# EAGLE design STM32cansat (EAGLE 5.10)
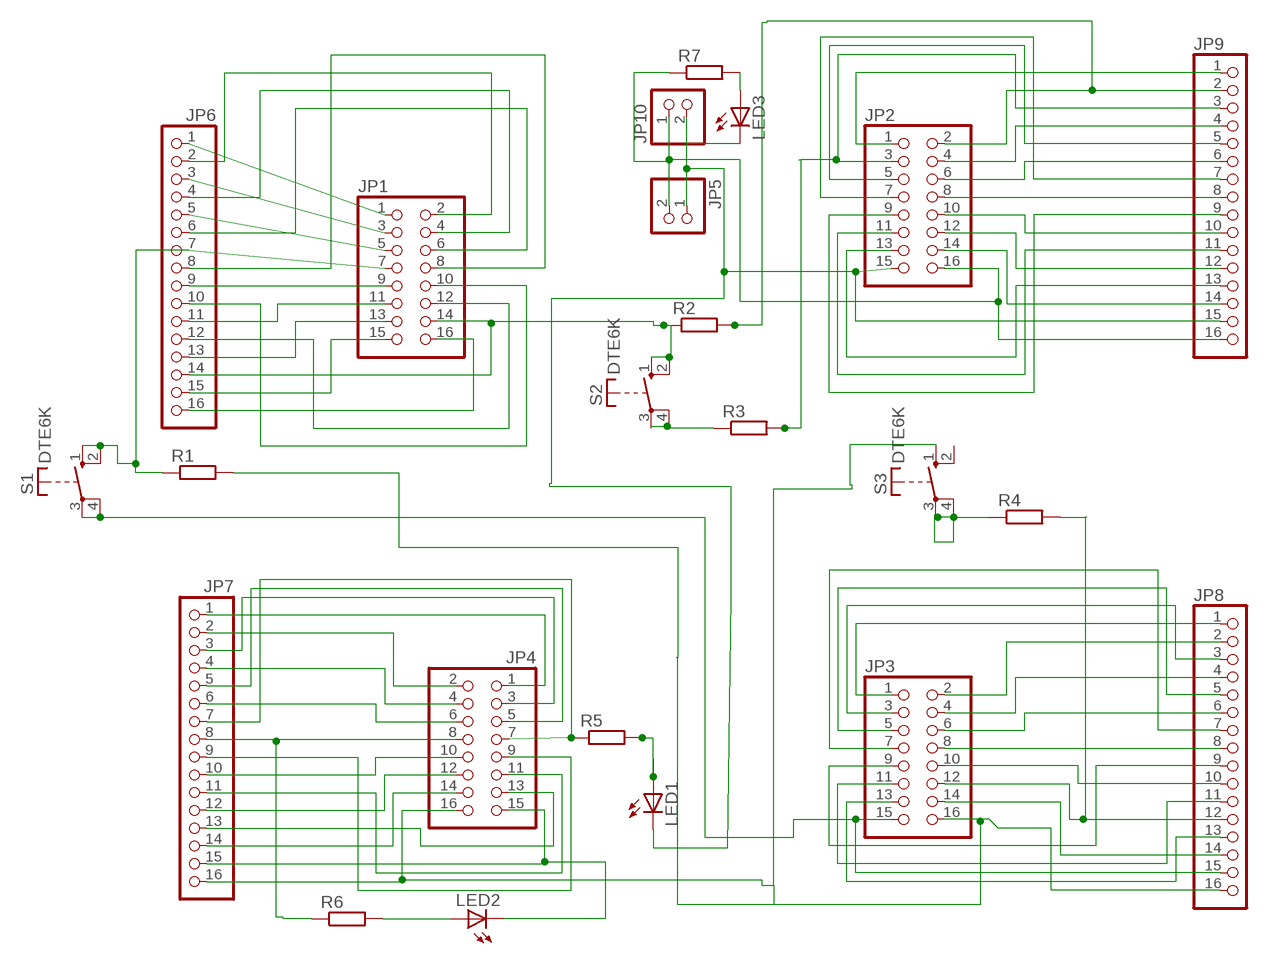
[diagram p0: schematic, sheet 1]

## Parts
JP1  PINHD-2X8  [2X08]
JP2  PINHD-2X8  [2X08]
JP3  PINHD-2X8  [2X08]
JP4  PINHD-2X8  [2X08]
JP5  PINHD-1X2  [1X02]
JP6  PINHD-1X16  [1X16]
JP7  PINHD-1X16  [1X16]
JP8  PINHD-1X16  [1X16]
JP9  PINHD-1X16  [1X16]
JP10  PINHD-1X2  [1X02]
LED1  LED3MM  [LED3MM]
LED2  LED3MM  [LED3MM]
LED3  LED3MM  [LED3MM]
R1  R-EU_0207/10  [0207/10]
R2  R-EU_0207/10  [0207/10]
R3  R-EU_0207/10  [0207/10]
R4  R-EU_0207/10  [0207/10]
R5  R-EU_0207/10  [0207/10]
R6  R-EU_0207/10  [0207/10]
R7  R-EU_0309/10  [0309/10]
S1  DTE6K  [DTE6K]
S2  DTE6K  [DTE6K]
S3  DTE6K  [DTE6K]

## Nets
N$1: JP1.1 JP6.1
N$3: JP1.2 JP6.2
N$4: JP1.3 JP6.3
N$6: JP1.4 JP6.4
N$7: JP1.5 JP6.5
N$8: JP1.6 JP6.6
N$9: JP1.7 JP6.7 R1.1 S1.1(S) S1.2(S)
N$10: JP1.8 JP6.8
N$11: JP1.9 JP6.9
N$12: JP1.11 JP6.11
N$13: JP1.13 JP6.13
N$14: JP1.15 JP6.15
N$15: JP1.16 JP6.16
N$16: JP1.14 JP6.14 R2.1 S2.1(S) S2.2(S)
N$17: JP1.12 JP6.12
N$18: JP1.10 JP6.10
N$19: JP2.8 JP9.8
N$20: JP2.6 JP9.6
N$21: JP2.4 JP9.4
N$22: R4.1 S3.4(P)
N$23: JP2.10 JP9.10
N$24: JP2.12 JP9.12
N$25: JP2.14 JP9.14
N$28: JP2.13 JP9.13
N$29: JP2.11 JP9.11
N$30: JP2.9 JP9.9
N$31: JP2.1 JP9.1
N$32: JP2.3 JP9.3 R3.2
N$33: JP2.5 JP9.5
N$34: JP2.7 JP9.7
N$35: JP4.8 JP7.8 R6.1
N$36: JP4.6 JP7.6
N$37: JP4.4 JP7.4
N$38: JP4.2 JP7.2
N$39: JP4.10 JP7.10
N$40: JP4.12 JP7.12
N$41: JP4.14 JP7.14
N$44: JP4.13 JP7.13
N$45: JP4.11 JP7.11
N$46: JP4.9 JP7.9
N$47: JP4.1 JP7.1
N$49: JP4.3 JP7.3
N$50: JP4.5 JP7.5
N$51: JP4.7 JP7.7 R5.1
N$54: JP3.8 JP8.8
N$55: JP3.6 JP8.6
N$56: JP3.4 JP8.4
N$57: JP3.2 JP8.2
N$58: JP3.1 JP8.1
N$59: JP3.3 JP8.3
N$60: JP3.5 JP8.5
N$61: JP3.7 JP8.7
N$62: JP3.10 JP8.10
N$63: JP3.12 JP8.12 R4.2
N$64: JP3.14 JP8.14
N$68: JP3.16 JP4.16 JP7.16 JP8.16 R1.2 S3.1(S)
N$126: S3.3(P)
N$129: JP3.13 JP8.13
N$130: JP3.11 JP8.11
N$131: JP3.9 JP8.9
N$137: JP3.15 JP8.15 S1.3(P) S1.4(P)
N$144: JP2.2 JP9.2 R2.2
N$151: R3.1 S2.4(P)
N$157: LED2.A R6.2
N$159: LED1.A R5.2
N$203: LED3.A R7.2
N$210: JP2.15 JP5.1 JP9.15 JP10.2 LED1.K(C) LED3.K(C)
N$212: JP2.16 JP5.2 JP9.16 JP10.1 R7.1
N$221: JP4.15 JP7.15 LED2.K(C)
Unconnected: S2.3(P) S3.2(S)

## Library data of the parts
JP1-JP4 = pinhead:PINHD-2X8: PIN HEADER
JP5 JP10 = pinhead:PINHD-1X2: PIN HEADER
JP6-JP9 = pinhead:PINHD-1X16: PIN HEADER
LED1-LED3 = led:LED: LED
R1-R7 = rcl:R-EU_: RESISTOR, European symbol
S1-S3 = switch-misc:DT: ITT SWITCH

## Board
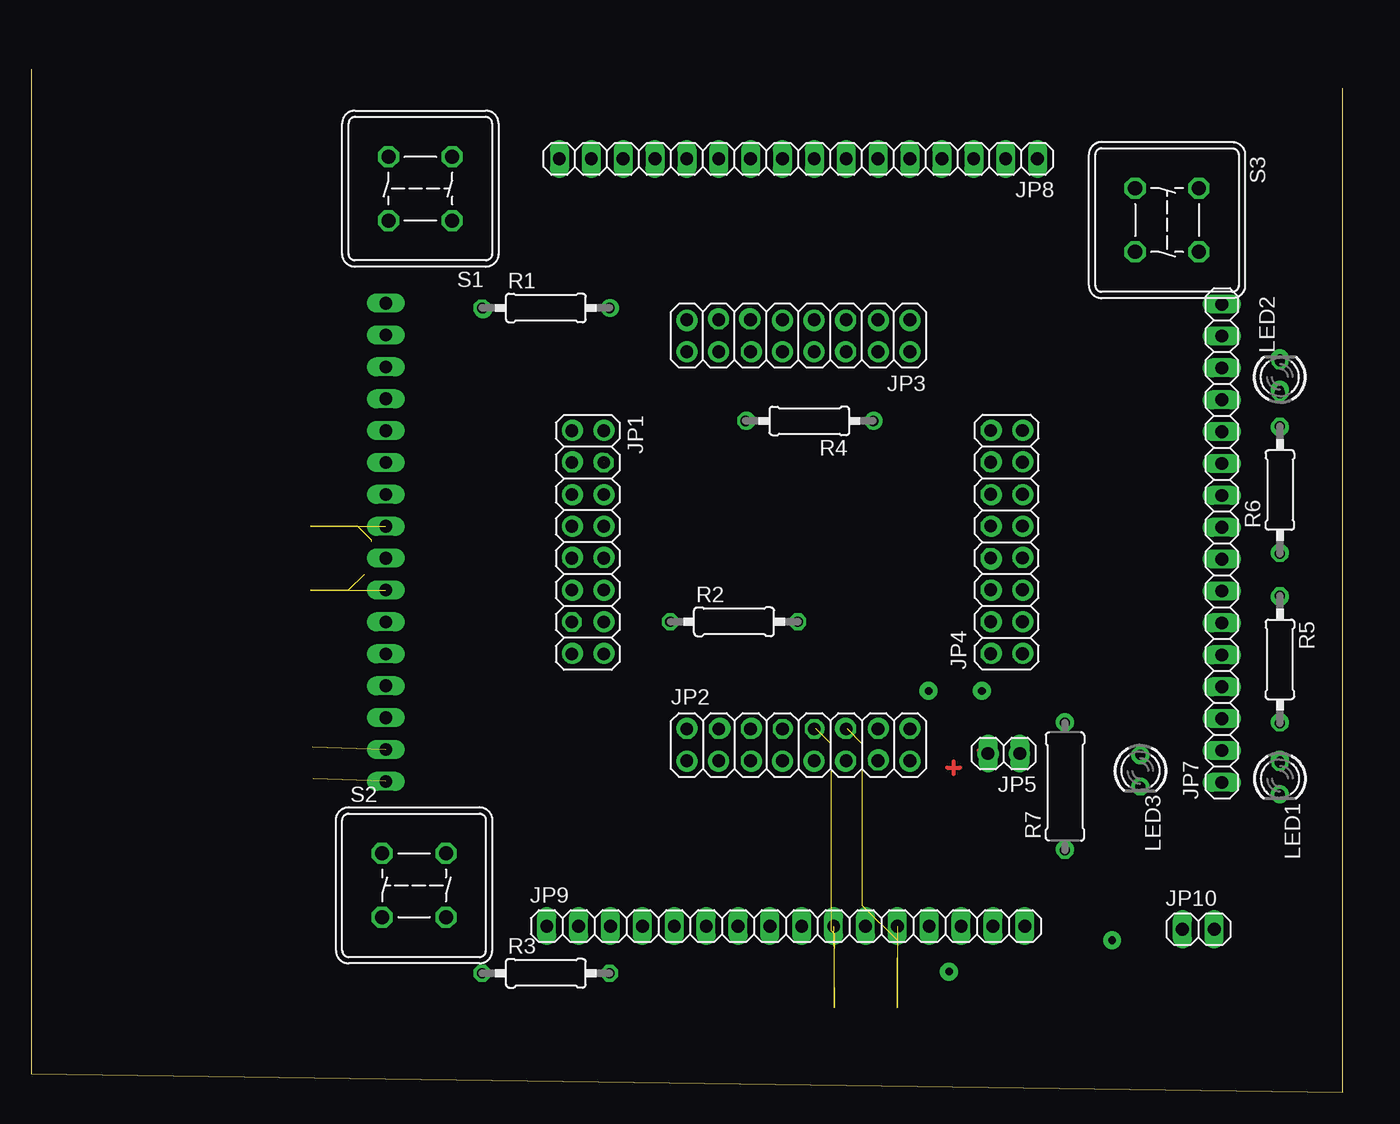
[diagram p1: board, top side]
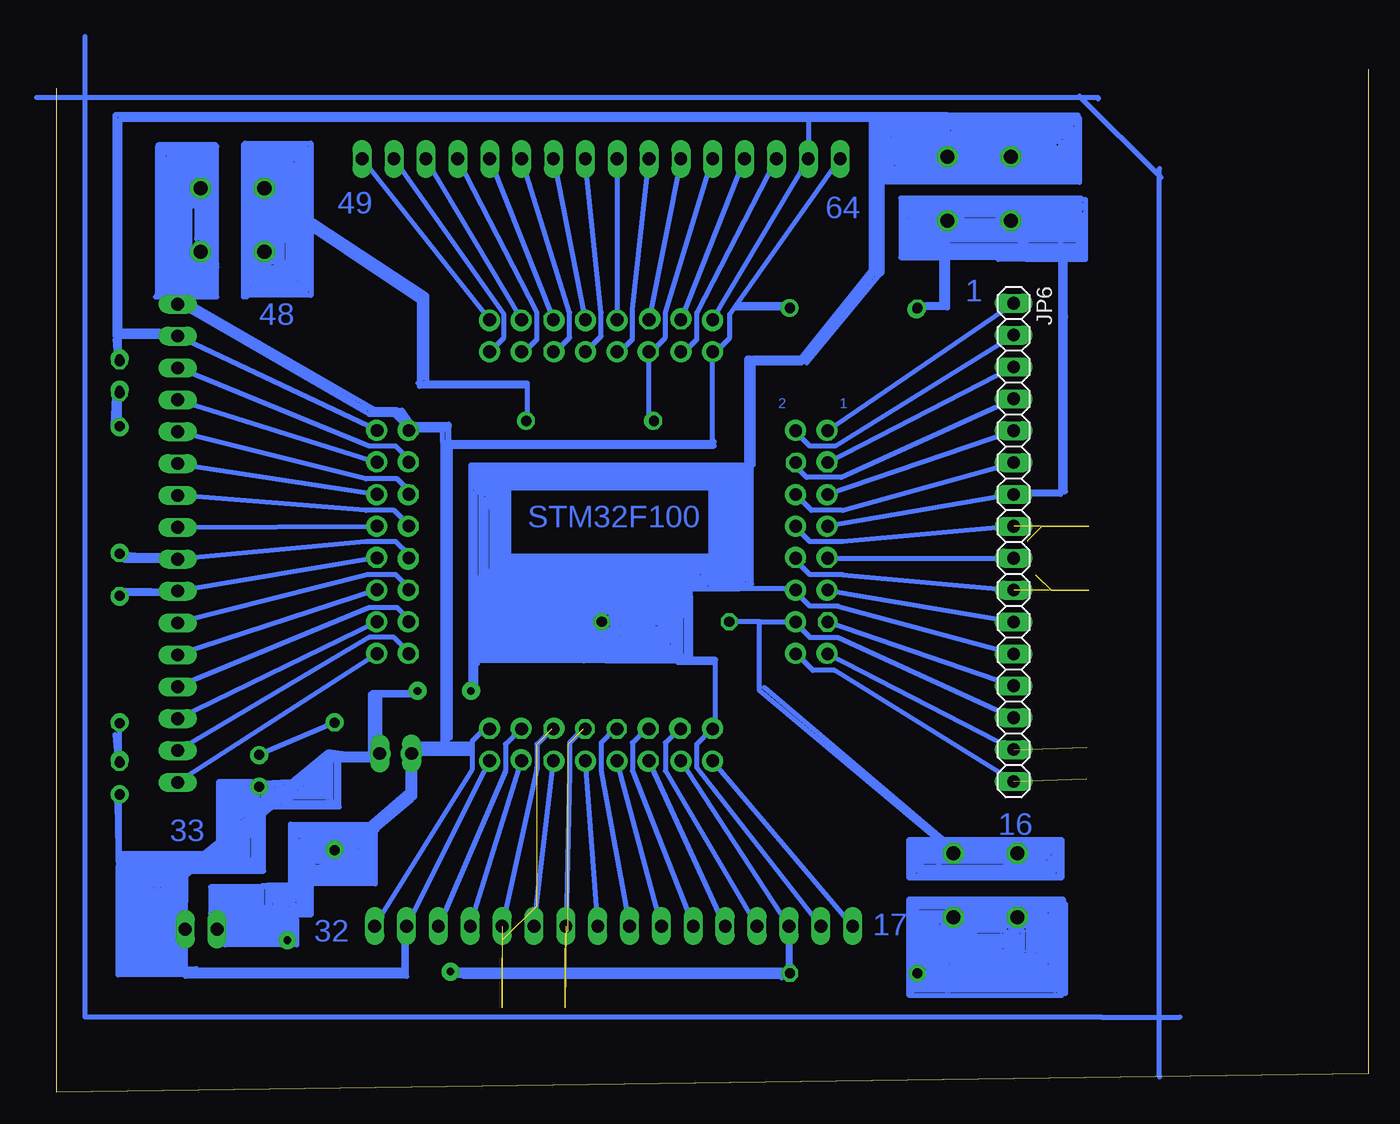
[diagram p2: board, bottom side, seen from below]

Size 104.5 x 81.5 mm. Coordinates in mm from the lower left corner, seen from the top.
Outline: 104.5,80 104.5,0 0,1.5 0,81.5
Copper layers (1*16): Top 0.035mm / dielectric 1.5mm / Bottom 0.035mm
Design rules "default": minimum track width 10mil, minimum drill 24mil, track to track 8mil, track to pad 8mil, pad to pad 8mil, via to via 8mil, smd to smd 8mil, copper to edge 40mil, drill to drill 8mil, minimum pad ring 10mil, minimum via ring 8mil, stop-mask expansion 4mil, vias tented up to drill 0mil, thermal gap 10mil

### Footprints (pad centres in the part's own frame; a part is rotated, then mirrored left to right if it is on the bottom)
2X08 = drill 1.016 octagon: 1 -8.89,-1.27; 2 -8.89,1.27; 3 -6.35,-1.27; 4 -6.35,1.27; 5 -3.81,-1.27; 6 -3.81,1.27; 7 -1.27,-1.27; 8 -1.27,1.27; 9 1.27,-1.27; 10 1.27,1.27; 11 3.81,-1.27; 12 3.81,1.27; 13 6.35,-1.27; 14 6.35,1.27; 15 8.89,-1.27; 16 8.89,1.27
1X02 = drill 1.016 long: 1 -1.27,0; 2 1.27,0
1X16 = drill 1.016 long: 1 -19.05,0; 2 -16.51,0; 3 -13.97,0; 4 -11.43,0; 5 -8.89,0; 6 -6.35,0; 7 -3.81,0; 8 -1.27,0; 9 1.27,0; 10 3.81,0; 11 6.35,0; 12 8.89,0; 13 11.43,0; 14 13.97,0; 15 16.51,0; 16 19.05,0
LED3MM = drill 0.813 octagon: A -1.27,0; K 1.27,0
0207/10 = drill 0.813 octagon: 1 -5.08,0; 2 5.08,0
0309/10 = drill 0.813 octagon: 1 -5.08,0; 2 5.08,0
DTE6K = drill 1.118 octagon: 1 -2.54,2.54; 2 2.54,2.54; 3 2.54,-2.54; 4 -2.54,-2.54

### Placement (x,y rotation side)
JP1  44.34,43.83 270 top
JP2  61.12,27.69 0 top
JP3  61.12,60.28 180 top
JP4  77.72,43.85 90 top
JP5  77.5,27 180 top
JP6  28.25,43.83 270 bottom
JP7  94.88,43.75 90 top
JP8  61.12,74.38 180 top
JP9  60.12,13.25 0 top
JP10  93,13 0 top
LED1  99.5,25 270 top
LED2  99.5,57 90 top
LED3  88.38,25.62 270 top
R1  41,62.5 0 top
R2  56,37.5 0 top
R3  41,9.5 0 top
R4  62,53.5 180 top
R5  99.5,34.5 270 top
R6  99.5,48 90 top
R7  82.38,24.38 90 top
S1  31,72 180 top
S2  30.5,16.5 0 top
S3  90.5,69.5 270 top

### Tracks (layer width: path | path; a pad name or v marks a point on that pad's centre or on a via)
N$1
  Bottom 0.406: JP1.1 JP6.1
N$2
  Top 0.305: 75.62,27.12 75.5,27.25
N$3
  Bottom 0.406: JP1.2 45.62,52.62 44.5,51.5 42.5,51.5 JP6.2
N$4
  Bottom 0.406: JP1.3 JP6.3
N$5  (via drill 0.6 pad 1.68)
  other vias: 76.25,27
N$6
  Bottom 0.406: JP1.4 45.62,49.87 44.75,49 42,49 JP6.4
N$7
  Bottom 0.406: JP1.5 JP6.5
N$8
  Bottom 0.406: JP1.6 45.62,47.62 44.38,46.38 41.88,46.38 JP6.6
N$9
  Bottom 0.406: JP1.7 JP6.7 24.5,47.64 24.5,69.5 28.46,69.5 S1.2 S1.1 33.54,62.5 | 33.54,62.5 R1.1 | 33.54,62.5 33.5,62.5
N$10  (4 unrouted)
  Bottom 0.406: JP1.8 45.62,44.99 44.5,43.88 41.88,43.88 JP6.8
N$11
  Bottom 0.406: JP1.9 JP6.9
N$12
  Bottom 0.406: JP1.11 JP6.11
N$13
  Bottom 0.406: JP1.13 JP6.13
N$14  (1 unrouted)
  Bottom 0.406: JP6.15 JP1.15
N$15  (1 unrouted)
  Bottom 0.406: JP1.16 45.56,34.94 44.25,33.62 42.5,33.62 JP6.16
N$16
  Bottom 0.406: JP6.14 42.25,36.25 44.5,36.25 45.62,37.37 JP1.14 48.5,37.48 | 48.5,37.48 48.5,37.5 | 48.5,37.48 48.5,32 S2.2 S2.1 | 48.5,37.48 R2.1
N$17
  Bottom 0.406: JP1.12 45.62,39.87 44.5,38.75 42.25,38.75 JP6.12
N$18  (3 unrouted)
  Bottom 0.406: JP1.10 45.62,42.37 44.5,41.25 41.88,41.25 JP6.10
N$19
  Bottom 0.406: JP2.8 60.04,28.96 61.12,27.88 61.12,25.62 JP9.8
N$20
  Bottom 0.406: JP2.6 57.54,28.96 58.62,27.88 58.62,25.62 JP9.6
N$21
  Bottom 0.406: JP2.4 54.91,28.96 56,27.88 56,25.62 JP9.4
N$22
  Bottom 0.406: R4.1 67,53.5 67,56.5 | 67,56.5 75,56.5 | 75,56.5 75,63.5 S3.4 | 75.75,56.5 75,56.5 | 67,56.5 67.12,56.25 75.62,56.25 75.62,58 | 75.62,63.38 75.62,58 | 75.62,58 75.5,57.5
N$23  (6 unrouted)
  Bottom 0.406: JP2.10 62.54,28.96 63.62,27.88 63.62,25.5 JP9.10
N$24  (6 unrouted)
  Bottom 0.406: JP2.12 65.04,28.96 66.25,27.75 66.25,25.88 JP9.12
N$25
  Bottom 0.406: JP2.14 67.54,28.96 68.75,27.75 68.75,25.62 JP9.14
N$27
  Bottom 0.406: 87.25,73.12 88.75,73.12 88.75,72.88 | 87.38,67.62 87.38,70.88 87.62,70.88 | 89.62,63.38 89.62,75.5 89.5,75.62 84.25,75.62 84.25,63.5 89.25,63.5 89.38,63.38 89.38,75.38 84.75,75.38 84.62,75.25 84.62,63.88 89.25,63.88 89.25,75 85,75 84.88,75.12 84.88,64.38 85.12,64.12 88.75,64.12 89,64.38 89,72.38 89,72.88 | 89,72.88 89,74.75 85.25,74.75 85.12,74.62 85.12,64.38 88.62,64.38 88.62,72.62 | 88.62,72.88 88.62,74.25 88.75,74.38 85.38,74.38 85.38,64.88 85.62,64.62 88.38,64.62 88.5,64.75 88.5,67.38 89.12,68 88.5,68 88.25,67.75 88.25,71 88.38,71.12 85.62,71.12 85.62,65.12 85.88,64.88 88.12,64.88 88.12,65.62 | 88.12,65.62 88.12,66.12 87.5,66.12 | 87.12,66.12 85.75,66.12 85.75,65.5 86,65.25 88,65.25 88,65.62 87.88,65.75 86.38,65.75 | 86.12,65.75 86,65.88 86,65.62 86.75,65.62 | 88.12,65.62 86.75,65.62 | 86.75,65.62 86.38,66 | 86.38,66 85.88,66.5 85.88,67.88 | 85.88,67.88 85.88,73.88 86,74 85.75,74 85.75,71.88 85.62,71.75 87,71.75 87.12,71.62 86,71.62 85.75,71.38 85.75,71.5 86.75,71.5 87,71.25 87.38,71.25 87.75,70.88 | 87.75,70.88 87.88,70.75 87.88,68 87.75,67.88 86.12,67.88 | 85.88,67.88 86.12,67.88 | 86.12,67.88 86.12,74 88.5,74 88.5,73.62 86.12,73.62 86.12,65.75 | 86.12,65.75 86.38,65.75 | 86.38,65.75 86.38,66 | 86.38,66 86.5,66 86.5,73.88 86.62,73.88 | 86.88,73.88 86.62,73.88 | 86.62,73.88 86.62,66 87,66 87,72.62 | 87,72.62 87,72.88 | 87,72.88 87,73.75 87.38,73.75 87.38,73.25 87.12,73.25 87.12,66.12 | 87.12,66.12 87.5,66.12 | 87.5,66.12 87.5,66.25 | 87.75,70.88 87.62,70.88 | 87.62,70.88 87.62,68.12 | 87,72.62 88.62,72.62 | 88.62,72.62 88.62,72.88 | 88.62,72.88 88.5,72.88 88.5,73.38 87.5,73.38
  Bottom 0.406: 88.75,72.88 87,72.88 | 88.75,72.88 89,72.88
N$28
  Bottom 0.406: JP9.13 JP2.13
N$29
  Bottom 0.406: JP9.11 JP2.11
N$30
  Bottom 0.406: JP2.9 JP9.9
N$31
  Bottom 0.406: JP9.1 JP2.1
N$32
  Bottom 0.406: JP2.3 JP9.3 46.08,13.25 R3.2
N$33
  Bottom 0.406: JP9.5 JP2.5
N$34
  Bottom 0.406: JP9.7 JP2.7
N$35
  Bottom 0.406: JP4.8 76.44,42.82 77.5,43.88 79.88,43.88 JP7.8 R6.1
N$36
  Bottom 0.406: JP4.6 76.44,40.2 77.5,41.25 79.75,41.25 JP7.6
N$37
  Bottom 0.406: JP4.4 76.44,37.7 77.38,38.62 79.62,38.62 JP7.4
N$38
  Bottom 0.406: JP4.2 76.42,34.96 76.38,35 77.62,36.25 79.62,36.25 JP7.2
N$39
  Bottom 0.406: JP4.10 76.44,45.2 77.62,46.38 79.88,46.38 JP7.10
N$40
  Bottom 0.406: JP4.12 76.44,47.95 77.38,48.88 79.88,48.88 JP7.12
N$41
  Bottom 0.406: JP4.14 76.44,50.45 77.5,51.5 79.62,51.5 JP7.14
N$42
  Bottom 0.406: 92.62,73.25 95.25,73.25 | 95.25,73.25 95.38,73.25 95.38,73.38 95.25,73.38 95.25,73.25 | 95.25,73.25 95.25,72.12 95,72.12 95,73 92.75,73
N$43  (via drill 0.6 pad 1.42)
  Bottom 0.406: 61.12,37.62 61.25,37.62 61.25,37.88 | 61.25,37.88 61.25,40.12 | 45.75,40.12 50.12,40.12 | v71.5,32 71.5,36.12 | 71.5,36.62 71.5,50 50.12,50 | 50,50 49,50 49,58.5 45.25,58.5 39.62,65.5 39.62,77.38 39.38,77.38 | 50.12,40.25 50.12,50 | 50.12,50 50,50 | 50,50 50,49.75 | 61.25,40.12 50.12,40.12 | 50.12,40.12 50.12,40.25 | 50.12,40.25 52.38,40.25 52.38,42.62 | 52.38,42.75 52.38,48.75 | 52.38,48.75 52.38,48.88 | 52.38,49.12 52.38,49.62 50.38,49.62 50.38,40.62 51.88,40.62 51.88,40.5 52.12,40.5 52.12,49.5 51.75,49.5 | 51.62,49.5 50.75,49.5 50.75,41.12 50.5,41.12 50.5,41 51.75,41 51.75,40.88 51.62,40.88 51.62,41.5 | 51.62,48.12 51.62,49.5 | 51.62,49.5 51.75,49.5 | 51.75,49.5 51.75,49.25 50.88,49.25 50.88,41.25 51.12,41.25 | 51.38,41.25 51.12,41.25 | 51.12,41.25 51.12,48.88 51.5,48.88 51.5,41.5 51.62,41.5 | 51.62,41.5 51.62,48.12 | 51.62,48.12 68.5,48.12 | 68.62,48.12 71.12,48.12 71.12,49.75 52.5,49.75 52.5,49.38 71,49.38 71,49 52.38,49 | 52.38,49 52.38,48.88 | 52.38,48.88 52.62,48.88 52.62,48.5 68.62,48.5 | 70.88,48.5 68.62,48.5 | 68.62,48.5 68.62,48.12 | 68.62,48.12 68.5,48.12 | 68.5,48.12 68.5,42.75 52.38,42.75 | 52.38,42.75 52.38,42.62 | 52.38,42.62 52.75,42.62 52.75,42.5 | 52.75,42.5 52.75,40.5 71.12,40.5 | 71.12,40.5 71.12,40.38 | 71.12,40.5 71.12,41 | 71.12,41 71.12,47.88 68.88,47.88 68.88,42.25 53,42.25 53,41 58.88,41 | 58.88,41 70.62,41 | 71.12,41 70.62,41 | 70.62,41 70.62,47.75 69.25,47.75 69.25,42 53.25,42 53.25,41.88 53.38,41.88 53.38,41.38 70.25,41.38 | 70.25,41.38 70.25,41.25 | 70.25,41.38 70.25,47.38 69.62,47.38 | 69.62,47.38 69.62,47.5 | 69.62,47.38 69.62,41.75 52.62,41.75 52.62,41.5 49.88,41.5 | 49.88,40.88 49.88,40.5 49.12,40.5 49.12,49.88 49.5,49.88
  Bottom 0.406: 49.5,49.88 49.5,40.88 49.88,40.88 | 49.88,41.5 49.88,40.88 | 49.88,41.5 49.88,49.38 49.62,49.38 49.62,49.88 49.5,49.88 | 49.5,49.88 49.5,58.5 49.38,58.5 | 49.25,58.5 49.38,58.5 | 49.38,58.5 49.38,49.62 70,49.62 70,46.62 69.88,46.62 69.88,41.62 61.38,41.62 61.38,40.38 61.25,40.38 61.25,40.12 | 61.25,37.88 71.25,37.88 71.25,38 71.12,38 71.12,40.25 71,40.25 | 70.75,40.25 61.38,40.25 61.38,40 61.5,40 61.5,38 61.88,38 | 70.25,38 70.62,38 70.62,38.62 | 70.62,38.62 70.62,39.62 | 70.62,39.62 70.62,39.88 | 70.62,39.88 70.38,39.88 | 70.38,39.88 61.88,39.88 | 61.88,39.88 61.88,38 | 61.88,38 70.25,38 | 70.25,38 70.25,38.62 70.38,38.62 70.38,39.38 62,39.38 | 62,39.38 62,39.5 | 62,39.38 62,38.25 70,38.25 70,38.38 70.38,38.38 70.38,39.88 | 61.88,39.88 54.38,39.88 | 54.38,39.88 54.38,40 | 54.38,39.88 54.38,34.75 71.38,34.75 71.38,34.5 71.25,34.5 | 71.25,34.5 71.25,38.12 70.12,38.12 70.12,38.88 | 70.12,38.88 70.12,39.12 54.25,39.12 | 54,39.12 54.25,39.12 | 54.25,39.12 54.25,39.5 | 54.25,39.5 61.12,39.5 | 54.25,39.5 54,39.5 | 54,39.5 54,40.38 | 54,39.5 54,34.75 60.75,34.75 60.75,34.38 | 60.75,34.38 62.5,34.38 | 62.5,34.38 71.25,34.38 71.25,34.5 | 71.25,34.5 62.5,34.5 62.5,34.38 | 60.75,34.38 52.12,34.38 52.12,34.25 55,34.25 55,34.62 54.75,34.62 54.75,38.38 | 54.75,38.5 54.75,38.88 69.88,38.88 | 70.12,38.88 69.88,38.88 | 69.88,38.88 69.88,38.38 54.75,38.38 | 54.62,38 54.62,38.38 54.75,38.38 | 54.75,38.38 54.75,38.5 | 54.75,38.5 54.62,38.5 54.62,38.62 70.62,38.62 | 70.62,38.62 71,38.62 71,36.62 | 71,35.88 71,35.12 55,35.12 55,38.25 70.75,38.25 70.75,35.5 61.25,35.5 | 60.75,35.5 55.38,35.5 | 55.38,35.5 55.38,35.38 | 55.38,35.5 55.38,38 60.38,38 60.38,37.38 60.25,37.38 60.25,35.62 60.5,35.62 60.5,36.88 60.75,36.88
  Bottom 0.406: 60.88,36.88 60.75,36.88 | 60.75,36.88 60.75,35.88 | 60.75,35.88 55.75,35.88 55.75,37.88 60.12,37.88 60.12,36 56,36 56,37.62 59.88,37.62 59.88,36.12 56.62,36.12 56.62,36.25 56.38,36.25 56.38,37.38 60,37.38 60,37 | 60,37 59.5,37 | 59.5,37 59.5,36.5 | 59.5,36.5 59.25,36.5 | 59.25,36.5 56.88,36.5 | 56.88,36.5 56.88,37 | 56.88,37 56.5,37 | 56.88,37 59.5,37 | 60,37 60,36.12 71.5,36.12 | 71.5,36.12 71.5,36.62 | 71.5,36.62 71,36.62 | 71,36.62 71,35.88 | 71,35.88 60.75,35.88 | 60.75,35.88 60.75,35.5 | 60.75,35.5 61.25,35.5 | 61.25,35.5 61.25,36.88 70.62,36.88 | 70.62,36.88 70.62,37 | 70.62,36.88 70.62,36.62 61.75,36.62 | 61.38,36.62 61.75,36.62 | 61.75,36.62 61.75,37.62 70.38,37.62 70.38,37.25 61.62,37.25 61.62,37.38 | 56.12,36.88 59.25,36.88 59.25,36.5 | 56.88,36.5 56.5,36.5 | 59.5,36.5 70.62,36.5 70.62,36.25 71,36.25 71,40 70.62,40 70.62,39.88 | 70.62,39.62 59,39.62 59,40.75 51.88,40.75 51.88,41.62 52,41.62 52,49.12 52.38,49.12 | 52.38,49.12 52.38,49 | 52.38,48.75 71,48.75 71,48.62 70.75,48.62 70.75,40.25 | 70.75,40.25 71,40.25 | 71,40.25 71,40.75 58.88,40.75 58.88,41 | 52.75,42.5 69.38,42.5
N$44
  Bottom 0.406: JP7.13 JP4.13
N$45
  Bottom 0.406: JP7.11 JP4.11
N$46
  Bottom 0.406: JP7.9 JP4.9
N$47
  Bottom 0.406: JP4.1 JP7.1
N$48  (via drill 0.6 pad 1.68)
  other vias: 78.75,27
N$49
  Bottom 0.406: JP4.3 JP7.3
N$50
  Bottom 0.406: JP4.5 JP7.5
N$51
  Bottom 0.406: JP4.7 JP7.7 99,40 R5.1
N$52
  Bottom 0.406: 102.25,84.12 102.25,6 21.5,6 21.25,6 15,6
N$53
  Bottom 0.406: 106.12,79.25 21.5,79.25 21.5,79.12
N$54
  Bottom 0.406: JP3.8 62.37,59.01 61.12,60.25 61.12,62.12 JP8.8
N$55
  Bottom 0.406: JP3.6 64.74,59.01 63.62,60.12 63.62,62.12 JP8.6
N$56
  Bottom 0.406: JP3.4 67.24,59.01 66.25,60 66.25,62.12 JP8.4
N$57
  Bottom 0.406: JP3.2 69.99,59.01 68.88,60.12 68.88,62 JP8.2
N$58
  Bottom 0.406: JP8.1 JP3.1
N$59
  Bottom 0.406: JP8.3 JP3.3
N$60
  Bottom 0.406: JP8.5 JP3.5
N$61
  Bottom 0.406: JP8.7 JP3.7
N$62
  Bottom 0.406: JP3.10 59.62,59.01 58.62,60 58.62,62.38 JP8.10
N$63  (via drill 0.6 pad 1.42)
  Bottom 0.406: JP8.12 56,62.12 56,60.12 57.12,59.01 JP3.12 57.31,53.5 v57,53.5 R4.2
N$64
  Bottom 0.406: JP3.14 54.49,59.01 53.5,60 53.5,62.12 JP8.14
N$65  (via drill 0.7 pad 1.68)
  other vias: 43.12,52.75
N$66  (via drill 0.7 pad 1.68)
  other vias: 45.62,52.75
N$67  (1 unrouted)
N$68  (via drill 0.6 pad 1.42)
  Bottom 0.406: 73.38,28.25 73.12,28.25 73.12,51.88 73.25,51.88 | 73.25,51.88 73.38,51.88 | S3.1 95,72 95,63.5 JP7.16 79.62,54 77.62,54 76.44,52.82 JP4.16 73.75,52.75 73.75,51.75 | 50.34,62.74 50.88,62 50.88,60.12 51.99,59.01 JP3.16 52.25,51.75 73.75,51.75 | 50.34,62.74 JP8.16 | R1.2 v46.12,62.5 50.34,62.5 50.34,62.74 | 75.5,27.25 71.75,27.25 | 71.75,27.75 71.5,27.75 71.5,27.25 71.75,27.25 | 72,27.75 75.75,27.75 75.75,27.5 | 71.75,27.25 71.75,27.75 | 71.75,27.75 72,27.75 | 72,27.75 72,27.5 73.38,27.5 | 73.38,27.5 73.75,27.5 | 73.75,27.5 75.75,27.5 | 75.75,27.5 76,27.5 76,23.5 76.5,23.5 | 76.5,23.5 76.5,23.25 | 76.5,23.5 76.5,24 | 76.5,24 76.5,26.25 | 73.75,51.75 73.75,27.5 | 73.38,51.88 73.38,51.5 | 73.38,27.5 73.38,51.5 | 73.38,51.5 52.12,51.5 52.12,51.88 | 73.25,51.88 73.25,52.88 73.5,52.88 73.5,53 76.12,53 76.12,53.25 73.25,53.25 73.25,53 73.38,53 73.38,51.88 | 88.88,13.38 76.5,24 | 76.5,24 89.12,13.12
N$69  (via drill 0.7 pad 1.68)
  other vias: 45.62,47.62
N$70  (via drill 0.7 pad 1.68)
  other vias: 45.62,45.12
N$71  (via drill 0.7 pad 1.68)
  other vias: 45.62,42.62
N$72  (via drill 0.7 pad 1.68)
  other vias: 43.12,42.62
N$73  (via drill 0.7 pad 1.68)
  other vias: 43.12,45.12
N$74  (via drill 0.7 pad 1.68)
  other vias: 43.12,47.62
N$75  (via drill 0.7 pad 1.68)
  other vias: 45.62,40
N$76  (via drill 0.7 pad 1.68)
  other vias: 45.62,37.5
N$77  (via drill 0.7 pad 1.68)
  other vias: 45.62,35
N$78  (via drill 0.7 pad 1.68)
  other vias: 43.12,35
N$79  (via drill 0.7 pad 1.68)
  other vias: 43.12,40
N$80  (via drill 0.7 pad 1.68)
  other vias: 52.25,29
N$81  (via drill 0.7 pad 1.68)
  other vias: 54.88,29
N$82  (via drill 0.7 pad 1.68)
  other vias: 57.38,29
N$83  (via drill 0.7 pad 1.68)
  other vias: 62.38,26.38
N$84  (via drill 0.7 pad 1.68)
  other vias: 59.88,26.38
N$85  (via drill 0.7 pad 1.68)
  other vias: 57.38,26.38
N$86  (via drill 0.7 pad 1.68)
  other vias: 54.75,26.38
N$87  (via drill 0.7 pad 1.68)
  other vias: 52.25,26.38
N$88  (via drill 0.7 pad 1.68)
  other vias: 64.88,29
N$89  (via drill 0.7 pad 1.68)
  other vias: 67.5,29
N$90  (via drill 0.7 pad 1.68)
  other vias: 70,29
N$91  (via drill 0.7 pad 1.68)
  other vias: 70,26.38
N$92  (via drill 0.7 pad 1.68)
  other vias: 67.5,26.5
N$93  (via drill 0.7 pad 1.68)
  other vias: 64.88,26.38
N$94  (via drill 0.7 pad 1.68)
  other vias: 76.5,35
N$95  (via drill 0.7 pad 1.68)
  other vias: 79,35
N$96  (via drill 0.7 pad 1.68)
  other vias: 79,37.5
N$97  (via drill 0.7 pad 1.68)
  other vias: 79,40
N$98  (via drill 0.7 pad 1.68)
  other vias: 79,42.62
N$99  (via drill 0.7 pad 1.68)
  other vias: 79,45.12
N$100  (via drill 0.7 pad 1.68)
  other vias: 76.5,37.5
N$101  (via drill 0.7 pad 1.68)
  other vias: 76.5,40
N$102  (via drill 0.7 pad 1.68)
  other vias: 76.5,42.5
N$103  (via drill 0.7 pad 1.68)
  other vias: 76.5,45.12
N$104  (via drill 0.7 pad 1.68)
  other vias: 79,47.62
N$105  (via drill 0.7 pad 1.68)
  other vias: 76.5,47.62
N$106  (via drill 0.7 pad 1.68)
  other vias: 76.5,50.25
N$107  (via drill 0.7 pad 1.68)
  other vias: 79,50.25
N$108  (via drill 0.7 pad 1.68)
  other vias: 79,52.75
N$109  (via drill 0.7 pad 1.68)
  other vias: 76.5,52.75
N$110  (via drill 0.7 pad 1.68)
  other vias: 70,59
N$111  (via drill 0.7 pad 1.68)
  other vias: 70,61.5
N$112  (via drill 0.7 pad 1.68)
  other vias: 67.5,59
N$113  (via drill 0.7 pad 1.68)
  other vias: 67.5,61.5
N$114  (via drill 0.7 pad 1.68)
  other vias: 64.88,59
N$115  (via drill 0.7 pad 1.68)
  other vias: 64.88,61.5
N$116  (via drill 0.7 pad 1.68)
  other vias: 62.38,61.5
N$117  (via drill 0.7 pad 1.68)
  other vias: 62.38,59
N$118  (via drill 0.7 pad 1.68)
  other vias: 59.88,59
N$119  (via drill 0.7 pad 1.68)
  other vias: 59.88,61.5
N$120  (via drill 0.7 pad 1.68)
  other vias: 57.25,61.62
N$121  (via drill 0.7 pad 1.68)
  other vias: 57.38,59
N$122  (via drill 0.7 pad 1.68)
  other vias: 54.75,59
N$123  (via drill 0.7 pad 1.68)
  other vias: 54.75,61.62
N$124  (via drill 0.7 pad 1.68)
  other vias: 52.25,59
N$125  (via drill 0.7 pad 1.68)
  other vias: 52.25,61.5
N$127
  Top 0.305: 73,25.88 74,25.88
N$128
  Top 0.305: 73.5,26.38 73.5,25.38
N$129
  Bottom 0.406: JP8.13 JP3.13
N$130
  Bottom 0.406: JP8.11 JP3.11
N$131
  Bottom 0.406: JP8.9 JP3.9
N$132
  Bottom 0.406: 16.62,1.25 16.62,73.62
N$133  (via drill 0.6 pad 1.42)
  other vias: 43,37.5
N$134  (via drill 0.6 pad 1.42)
  other vias: 60,29
N$135  (via drill 0.6 pad 1.42)
  other vias: 62.5,29
N$136
  Bottom 0.406: 16.5,72.88 23,79.38
N$137
  Bottom 0.406: JP3.15 JP8.15 44.62,77.5 33.5,77.5 33.5,74.54 S1.4 S1.3
N$138  (via drill 0.6 pad 1.42)
  other vias: 65,29
N$139  (via drill 0.6 pad 1.42)
  other vias: 62.4,29
N$140  (via drill 0.6 pad 1.42)
  other vias: 64.85,29
N$141  (via drill 0.6 pad 1.42)
  other vias: 43.1,37.5
N$142
  Bottom 0.406: 48.88,58.12 45.12,58.12 45.12,58.62
N$143
  Bottom 0.406: 71,34.12 71.12,34.12 71.12,32.38
N$144
  Bottom 0.406: JP9.2 53.5,25.88 53.5,27.75 52.29,28.96 JP2.2 52.23,29.5 52,29.5 52,34.5 61,34.5 61,37.5 R2.2
N$145  (via drill 0.6 pad 1.42)
  other vias: 28,19
N$146  (via drill 0.6 pad 1.42)
  other vias: 33,19
N$147  (via drill 0.6 pad 1.42)
  other vias: 33.5,69.5
N$148  (via drill 0.6 pad 1.42)
  other vias: 28.5,69.5
N$149  (via drill 0.6 pad 1.42)
  other vias: 28.5,74.5
N$150  (via drill 0.6 pad 1.42)
  other vias: 33.5,74.5
N$151  (via drill 0.6 pad 1.42)
  Bottom 0.406: R3.1 36,9.5 36,14 v33,14 v28,14 27.96,14 S2.4
N$152  (via drill 0.6 pad 1.42)
  Bottom 0.406: v88,72 v88,67
N$154  (via drill 0.6 pad 1.42)
  other vias: 99.5,23.75
N$155  (via drill 0.6 pad 1.42)
  other vias: 99.5,43
N$156  (via drill 0.6 pad 1.42)
  other vias: 99.5,39.5
N$157  (via drill 0.6 pad 1.42)
  Bottom 0.406: R6.2 v99.5,56 LED2.A
N$158  (via drill 0.6 pad 1.42)
  other vias: 93,72.12
N$159  (via drill 0.6 pad 1.42)
  Bottom 0.406: LED1.A v99.5,26.5 R5.2
N$160  (via drill 0.6 pad 1.42)
  other vias: 99.5,29.5
N$161  (via drill 0.6 pad 1.42)
  other vias: 99.5,53
N$162  (via drill 0.6 pad 1.42)
  other vias: 93,67
N$163
  Bottom 0.406: 93,71.75 93,67.62
N$164  (via drill 0.6 pad 1.42)
  other vias: 67.12,53.5
N$165  (via drill 0.6 pad 1.42)
  other vias: 36,62.38
N$166
  Bottom 0.406: 92.5,71.38 92.5,67.62 92.75,67.62 92.75,71.25 94.75,71.25 94.75,71 94.62,71 94.62,72.38 | 94.62,72.38 93.88,72.38 | 94.62,72.38 94.88,72.38 94.88,72.5 94.75,72.5 94.75,65.38 94.38,65.38 94.38,71.62 93.75,71.62
N$167  (via drill 0.6 pad 1.42)
  other vias: 45.5,50.25
N$168
  Bottom 0.406: 93.25,70.88 94.12,70.88 94.12,66.25 | 94.12,66 94.12,65.75 92.5,65.75 92.5,65.5 95.75,65.5 95.75,64.88 | 96.38,63.62 92,63.62 92,63.88 96.25,63.88 96.25,64.25 92.12,64.25 92.12,64.12 92,64.12 92,64.5 96.25,64.5 96.25,75.25 92.12,75.25 92.12,75.12 92,75.12 92,64.88 95.75,64.88 | 95.75,64.88 96,64.88 96,74.88 92.25,74.88 92.25,65.25 95.62,65.25 95.62,74.5 92.62,74.5 92.62,74.62 92.5,74.62 92.5,72.75 95.25,72.75 | 95.38,72.75 95.25,72.75 | 95.25,72.75 95.25,73.88 | 95.25,74 95.25,74.25 92.75,74.25 92.75,74.12 92.62,74.12 92.62,73.62 95.5,73.62 95.5,73.88 95.25,73.88 | 95.25,73.88 95.25,74 | 95.25,74 92.75,74 92.75,73.75 | 95.75,64.88 95.75,64.62 | 92.38,66.25 93.88,66.25 | 94,66.25 94.12,66.25 | 94.12,66.25 94.12,66 | 94.12,66 94,66 | 92.12,66 94,66 | 94,66 94,66.25 | 94,66.25 93.88,66.25 | 93.88,66.25 93.88,70.62 93.38,70.62 | 93.25,70.62 93.38,70.62 | 93.38,70.62 93.38,68
N$169  (via drill 0.6 pad 1.42)
  other vias: 75.75,32
N$171
  Bottom 0.406: 76,31.62 79.25,31.62 79.25,28.5 78.75,28.5 | 78.75,28.5 78.75,28.25 | 78.75,28.5 78.75,31.5 79,31.5 79,28.88
N$172
  Bottom 0.406: 45,58.25 39.25,65.38 38.88,65.25 44.75,58.12
N$175
  Bottom 0.406: 76.75,53.5 76.75,53.75 77.38,54.38 79.5,54.38 79.62,54.5 80.12,54.5 80.25,54.62 94.25,62.75 94,63 78.88,54.25 77,54.38 76.38,53.5
N$176
  Bottom 0.406: 95.38,63.62 95.25,72 94,72
N$177
  Bottom 0.406: 99.88,60 99.75,58.25
N$178
  Bottom 0.406: 99.75,55 99.88,53.5
N$179
  Bottom 0.406: 100,53.12 99.88,55.5
N$180
  Bottom 0.406: 96.12,42.75 99,42.75
N$181
  Bottom 0.406: 96.25,42.38 99.12,42.38
N$182
  Bottom 0.406: 96.38,39.75 99.25,39.75
N$183
  Bottom 0.406: 99.88,28.5 99.75,26.75
N$186
  Bottom 0.406: 76.62,23.38 88.5,13.25
N$187
  Bottom 0.406: 88.88,13.25 91,13.25
N$188
  Bottom 0.406: 91,13.75 88.75,13.62
N$189
  Bottom 0.406: 76.88,12 76.88,9.38 77,9.75 | 77,9.75 94.5,9.62 94.62,12 | 77,9.75 94.12,9.75 94.12,9.88 93.38,9.88 93.38,9.5 77,9.5 77,9.62
N$190  (via drill 0.6 pad 1.42)
  other vias: 73.12,9.62
N$191  (via drill 0.6 pad 1.42)
  other vias: 86.12,12.12
N$192
  Bottom 0.406: 46,9.38 73,9.25
N$193
  Bottom 0.406: 46.62,9.62 72.75,9.75
N$194
  Bottom 0.406: 86.25,12.38 87.62,13.62
N$195
  Bottom 0.406: 86.12,12.75 87.25,13.75
N$196
  Bottom 0.406: 46.25,12 46.25,10
N$197
  Bottom 0.406: 33.38,19.75 48.12,32.25
N$198
  Bottom 0.406: 75.25,63.12 87.5,71.25
N$199
  Bottom 0.406: 75.25,62.75 87.75,71.12
N$200
  Bottom 0.406: 75.38,62.62 75.38,56.88
N$203
  Bottom 0.406: R7.2 LED3.A
N$205  (via drill 0.6 pad 1.42)
  other vias: 88.38,24.38
N$206  (via drill 0.6 pad 1.42)
  other vias: 88.38,26.88
N$207  (via drill 0.6 pad 1.42)
  other vias: 82.38,29.5
N$208  (via drill 0.6 pad 1.42)
  other vias: 82.38,19.38
N$209
  Bottom 0.406: 86,24.75 88,24.62 88.12,23.25 86.62,24.5 87.62,24.5 87.88,23.75 87.38,24.25
N$210
  Bottom 0.406: 88.88,24.75 91.62,24.75 91.62,19.75 91.38,20.75 88.5,23 88.75,23.75 91.38,23.75 | 91.38,23.75 91.38,24.12 | 91.38,24.12 91.38,24.5 89.12,24.5 88.88,23.12 91.38,21 91.38,23.75 | 91.38,24.12 89.38,24.12 89.12,23.25 91.12,21.62 91,23.5 89.38,23.5 91,22.12 90.88,23.25 89.88,23.12 90.88,22.75 91.75,19.62 92.62,19 99.5,19 | 88.3,22.69 82.88,27.12 81.75,27 | 88.3,22.69 94.5,17.62 | 75.75,31.88 79.38,31.88 79.38,31.75 79.5,31.75 79.5,27 | JP2.15 JP9.15 76.62,9.25 94.25,9.25 94.25,9.5 | 81.75,27 82.25,27 94.25,17.25 | 81.75,27 79.5,27 | 79.5,27 79,27 | 79,27 JP5.1 82.25,26.75 | 94.25,17.25 JP10.2 | 79,27 79,26.75 81.12,26.75 | 82.25,26.75 82.5,26.75 82.5,26.5 79.25,26.5 | 82.25,26.75 81.12,26.75 | 99.5,17.38 99.5,17.25 94.88,17.25 | 99.5,19 LED1.K | 94.25,17.25 94.88,17.25 | 94.25,17.25 82.25,26.75 | 94.25,9.5 94.25,17.25 | 79.5,27 79.5,26.88 | 81.12,26.75 81.75,27 | 94.88,17.25 94.88,13.75 94.5,13.75 94.62,17 | LED3.K 88.5,24.36 88.5,23.12 88.3,23.12 88.3,22.69 | 99.5,19 99.5,17.38 | 99.5,17.38 99.38,17.62 90.12,17.62 | 90.12,17.62 90.12,18.12 | 90.12,18.12 90.12,20.25 90.5,20.38 90.5,17.88 99.38,17.88 99.38,18.88 90.62,18.88 90.88,18.25 90.88,19.5 92.62,18 90.88,18.12 90.75,19.62 92,18.25 99.25,18.12 99.25,18.5 91.12,18.5 91.12,18.25 92.12,18.25 98.62,18 98.62,9.5 94.25,9.5 | 94.25,9.5 94.75,9.75 98.38,9.75 98.25,17 95.12,17 95,9.88 94.75,10 94.75,11.62 96.88,11.62 | 97.12,11.62 98.38,11.62 98.25,11.12 94.88,11.25 98.12,11.25 98.12,16.88 97.88,16.88 97.88,10.12 98.12,10.12 | 98.12,10.12 98.12,10 | 98.12,10.12 98.12,11 95.38,11 95.38,10 97.75,10 97.75,10.75 95.62,10.75 95.62,10.38 97.62,10.38 97.62,10.25 97.5,10.25 97.5,16.75 95.38,16.75 95.38,11.5 95.75,11.5 95.75,16.5 97.12,16.5
  Bottom 0.406: 97.38,16.5 97.12,16.5 | 97.12,16.5 97.12,11.62 | 97.12,11.62 96.88,11.62 | 96.88,11.62 96.88,16.12 96.62,16.12 | 96.38,16.12 96.12,16.12 | 96,16.12 96.12,16.12 | 96.12,16.12 96.12,11.88 96.5,11.88 96.5,12 96.38,12 96.38,16.12 | 96.38,16.12 96.62,16.12 | 96.62,16.12 96.62,12 | 90.12,17.62 88,17.62 88,22.12 88.38,22.12 88.38,17.88 89.75,17.88 | 90,17.88 89.75,17.88 | 89.75,17.88 89.75,18.12 89.88,18.12 89.88,20.62 88.75,20.62 88.75,21.25 89.25,21.25 89.25,20.88 88.62,20.88 | 88.62,20.88 88.62,21.5 | 88.62,20.88 88.62,18.12 89.62,18.12 | 90.12,18.12 89.62,18.12 | 89.62,18.12 89.62,18.5 89.5,18.5 | 89.5,18.5 89.5,20.5 88.88,20.5 88.88,18.5 89.25,18.5 | 89.5,18.5 89.25,18.5 | 89.25,18.5 89.25,20.38
N$211
  Bottom 0.406: 79,20.88 79.12,20.88 79.12,16.62 85.88,16.62 85.88,20.75 85.62,20.75 | 85.62,20.75 79.62,20.75 79.62,21 85.62,21 85.62,20.75 | 85.62,20.75 85.62,16.25 85.38,16.25 85.38,20.5 79.38,20.5 79.38,20.25 79.5,20.25 79.5,16.88 79.75,16.88 | 79.75,16.88 85,16.88 85,20.12 79.88,20.12 79.88,17.25 84.75,17.25 84.75,17.38 84.62,17.38 84.62,19.88 81.38,19.88 81.38,17.38 84.38,17.38 84.38,18.75 | 84.38,19.12 84.38,19.5 83,19.5 83,18.75 84.38,18.75 | 84.38,18.75 84.38,19.12 | 84.38,19.12 83.25,19.12 | 83.12,19.12 83.25,19.12 | 83.25,19.12 83.25,18.38 84.12,18.38 84.12,18 | 84.12,17.75 84.12,18 | 84.12,18 80.25,18 80.25,19.62 80.12,19.62 80.12,17.5 82.62,17.5 82.62,17.88 80.75,17.88 | 80.38,17.88 80.75,17.88 | 80.75,17.88 80.75,19.25 80.5,19.25 80.5,18.38 81,18.38 | 82.12,18.38 81,18.38 | 81,18.38 81,19 79.75,19 79.75,16.88
N$212
  Bottom 0.406: 84.88,21.12 84.25,21.12 84.25,14.12 85.38,14.12 | 85.38,14.12 91.25,14.12 91.25,13.75 85.38,13.75 | 85.38,13.75 85.38,14.12 | 85.38,13.75 85.38,11.75 91.12,11.75 91.12,13.38 85.75,13.38 | 85.75,13.38 85.75,13.5 | 85.75,13.38 85.75,13 | 85.75,13 85.75,12.62 87.5,12.62 | 90.88,12.62 87.5,12.62 | 87.5,12.62 87.5,13 | 87.5,13 85.75,13 | JP2.16 70.42,28.96 71.38,28 71.38,27 | 71.38,27 71.38,25.75 JP9.16 | 88.5,13 JP10.1 | 82.01,18.43 79.42,20.6 76.25,23.25 JP5.2 71.38,27 | 82.01,18.43 88.5,13 | R7.1 82.01,19.3 82.01,18.43 | 87.5,13 88,13 | 88.5,13 88,13 | 88,13 88,12 87,12 87,12.12 86.88,12.12 86.88,12.38 90.88,12.38 90.88,12 88.12,12 88.12,16.5 87.75,16.5 | 85.75,16.5 87.75,16.5 | 87.75,16.5 87.75,16.38 | 87.75,16.38 87.75,14.75 87.88,14.75 87.88,14.62 84.5,14.62 84.5,16 84.38,16 84.38,14.38 87.5,14.38 87.5,16.38 85.25,16.38 85.25,16.25 87.25,16.25 87.25,15.25 86.88,15.25 86.88,15.5 | 86.88,15.5 86.88,15.88 | 86.88,15.88 86.12,15.88 86.12,16 86.88,16 86.88,15.88 | 86.88,15.5 86.5,15.5 86.5,15.75 84.62,15.75 84.62,15.62 84.88,15.62 84.88,14.75 85.75,14.75 85.75,15.38 85.25,15.38 | 85.12,15.38 85.25,15.38 | 85.25,15.38 85.25,14.88 85.62,14.88 85.62,15 | 87.75,16.38 92.25,16.38 92.25,14.25 92,14.25 92,16.12 88.38,16.12 | 88.38,16.12 88.38,16.25 | 88.38,16.12 88.38,14.5 91.75,14.5 91.75,15.88 88.62,15.88 88.62,14.88 91.5,14.88 91.5,15.62 89,15.62 89,15.12 91.38,15.12 91.38,15.38 89.25,15.38
N$213
  Bottom 0.406: 85.75,20.38 85.88,20.38 85.88,21.38 79.5,21.38
N$214
  Bottom 0.406: 87.25,22.75 82,22.75 82,26.38 82.25,26.38 82.25,23.12 82.62,23.12 | 86.62,23.12 82.62,23.12 | 82.62,23.12 82.62,26.38 83,26.38 83,23.5 85.75,23.5 | 86.25,23.5 85.75,23.5 | 85.75,23.5 85.75,23.88 85.12,23.88 | 83.5,23.88 83.25,23.88 83.25,25.62 83.62,25.62 83.62,24.25 84,24.25 | 85,24.25 84,24.25 | 84,24.25 84,25.25 85.12,25.25 85.12,23.88 | 85.12,23.88 83.5,23.88 | 83.5,23.88 83.5,24 84.25,24 84.25,24.12 84.25,24.38 | 84.25,24.38 84.25,24.88 84.62,24.88 84.62,24.38 84.25,24.38
N$215
  Bottom 0.406: 93.5,9.38 99.62,9.38 99.62,18 99.25,18 99.25,17.38 | 99.75,23.12 99.62,17.38 99.38,17.38 | 99.25,17.38 94.25,17.38 | 99.25,17.38 99.38,17.38 | 99.38,17.38 99.38,9.75 99.12,9.75 | 99.12,9.75 98.75,9.75 98.75,17.12 99.12,17.12 99.12,9.75
N$216
  Bottom 0.406: 24.38,20.12 36.62,20.12 36.62,17.12 24.38,17.12 24.38,20.12
N$217
  Bottom 0.406: 24.25,15.38 36.62,15.38 36.62,7.75 24.38,7.75 24.38,8.38 24.25,8.38 24.25,15.25 24.5,15.25 24.5,15 24.12,15 24.12,7.88 24.62,7.88 24.62,15 36.25,15 | 36.38,15 36.25,15 | 36.25,15 36.25,10 24.88,10 24.88,10.38 25,10.38 25,14.75 36,14.75 36,14.38 33.62,14.38 33.62,9 | 33.62,8.88 33.62,8.12 36.25,8.12 | 36.38,8.12 36.25,8.12 | 36.25,8.12 36.25,8.38 | 36.25,8.75 36.25,8.88 33.62,8.88 | 33.62,8.88 33.62,9 | 33.62,9 33.88,9 33.88,13.62 35.88,13.62 35.88,10.25 34,10.25 34,10.38 34.25,10.38 34.25,10.5 | 34.25,10.5 34.25,13.25 35.62,13.25 35.62,10.5 34.62,10.5 | 34.25,10.5 34.62,10.5 | 34.62,10.5 34.62,13 35.38,13 35.38,9 34.25,9 34.25,9.62 35.25,9.62 35.25,9.75 35,9.75 35,9.25 34,9.25 34,9.62 35,9.62 35,11.25 34.88,11.25 34.88,12.88 35.12,12.88 35.12,8.38 36.25,8.38 | 36.25,8.38 36.25,8.75 | 36.25,8.75 33.75,8.75 | 33.75,8.75 33.75,8.5 35,8.5 | 33.75,8.75 33.75,9.75 25,9.75 25,8.12 33.38,8.12 33.38,9.5 25.25,9.5 25.25,8.5 33.12,8.5 33.12,9.25 25.5,9.25 25.5,9.12 25.38,9.12 | 25.38,9 25.38,8.75 33,8.75 33,9 25.38,9 | 25.38,9 25.38,9.12 | 25.38,9.12 25.25,9.12 25.25,14.5 27.25,14.5 27.25,14.38 27.12,14.38 27.12,10.12 32.5,10.12 32.5,10.25 32.38,10.25 32.38,14.5 28.75,14.5 28.75,14.25 32,14.25 32,10.38 25.62,10.38 25.62,14.12 26.88,14.12 26.88,13.25 33.25,13.25 33.25,10.38 32.62,10.38 | 32.5,10.38 32.62,10.38 | 32.62,10.38 32.62,13.12 33,13.12 33,10.62 28.88,10.62 | 28.5,10.62 25.75,10.62 25.75,10.75 25.88,10.75 25.88,13.88 26.62,13.88 26.62,13.75 26.75,13.75 26.75,10.5 26.25,10.5 26.25,11.25 26.38,11.25 26.38,13.62 26.12,13.62 26.12,10.88 31.75,10.88 31.75,13.62 28.5,13.62 28.5,10.62
  Bottom 0.406: 28.5,10.62 28.88,10.62 | 28.88,10.62 28.88,12.88 31.5,12.88 31.5,11.25 27.5,11.25 27.5,12.88 28.38,12.88 28.38,11.5 27.88,11.5 27.88,12.5 28.12,12.5 28.12,11.88 29.25,11.88 | 29.25,11.88 29.25,11.62 31.25,11.62 31.25,12.5 29.25,12.5 29.25,11.88 | 29.25,11.88 30.88,11.88 30.88,12.25 29.5,12.25
N$218
  Bottom 0.406: 24.5,19.75 36.38,19.75 36.38,19.62 36.25,19.62 36.25,17.25 24.62,17.25 24.62,19.38 32.38,19.38 32.38,19.5 35.88,19.5 35.88,17.62 25,17.62 25,19.12 27.12,19.12 27.12,17.88 25.38,17.88 25.38,18.75 26.88,18.75 26.88,18.12 25.75,18.12 25.75,18.38 28.88,18.38 | 28.88,18.38 35.75,18.38 35.75,18.25 35.62,18.25 35.62,19.25 33.88,19.25 33.88,18.62 35.25,18.62 35.25,19 34.25,19 34.25,17.88 35.5,17.88 35.5,18 27.38,18 27.38,18.12 28.88,18.12 28.88,18.38 | 28.88,18.38 28.88,18.75 32.38,18.75 32.38,18.62
N$220
  Bottom 0.406: 34.12,75.5 37.25,75.5 37.25,75.38 37.38,75.38 37.38,74.38 34.38,74.38 34.38,75.25 | 34.38,75.25 34,75.25 | 34.38,75.25 37.12,75.25 37.12,74.5 34.75,74.5 34.75,75 36.88,75 36.88,74.75 34.88,74.75
N$221  (via drill 0.6 pad 1.42)
  Bottom 0.406: 27.88,73.75 27.75,73.75 27.75,75.12 25.25,75.12 25.25,74.25 | 23.25,77 23.25,72.75 38.62,72.75 38.62,76.88 23.62,76.88 23.62,73 38.38,73 38.38,73.12 38.75,73.12 38.75,65.25 39.12,65.25 39.12,76.38 | 39.38,65.5 39.25,77.25 39.12,77.25 | 39,77.25 39.12,77.25 | 39.12,77.25 39.12,76.38 | 33.75,75.12 33.88,75.12 33.88,76.38 | 33.88,76.5 33.88,77.25 33.75,77.25 33.75,77.62 33.5,77.62 33.5,77.88 | 84.38,77.5 99.5,77.5 99.5,60.5 | JP4.15 JP7.15 99.5,60.5 | LED2.K v99.5,58.5 99.5,60.5 | 33.5,77.88 84.38,77.88 | 84.38,77.88 84.38,77.5 | 44.62,77.5 84.38,77.5 | 84.38,77.88 99.88,77.88 99.88,60.25 96.25,60.25 96.25,60.62 99.62,60.62 | 33.5,77.88 23.12,77.88 23.12,77.62 23,77.62 23,72.5 38.88,72.5 | 38.88,72.5 38.88,72.25 | 38.88,72.5 38.88,77.25 23.38,77.25 23.38,77.62 33.62,77.62 33.62,77.75 | 39.12,76.38 33.88,76.38 | 33.88,76.38 33.88,76.5 | 33.88,76.5 34.62,76.5 34.62,76.75 38.38,76.75 38.38,76.5 38.25,76.5 38.25,73.25 24,73.25 24,73.5 23.88,73.5 23.88,76.5 33.12,76.5 33.12,76.12 | 33.12,76.12 33.12,76 | 33.12,76 37.88,76 37.88,75.88 38,75.88 38,73.62 24.25,73.62 24.25,73.88 24.12,73.88 24.12,76.12 33.12,76.12 | 33.12,76 33.12,75.25 24.5,75.25 24.5,75.75 37.75,75.75 37.75,75.62 37.62,75.62 37.62,74 25.25,74 | 24.88,74 24.62,74 24.62,73.88 24.5,73.88 24.5,75 25,75 25,75.62 32.62,75.62 | 32.88,75.62 32.62,75.62 | 32.62,75.62 32.62,74.25 29.25,74.25 29.25,75 32.38,75 32.38,74.62 29.62,74.62 29.62,74.75 | 25.25,74.25 25.25,74 | 25.25,74 24.88,74 | 24.88,74 24.88,73.88 | 24.88,74 24.88,74.75 27.62,74.75 27.62,74.25 25.38,74.25 | 25.25,74.25 25.38,74.25 | 25.38,74.25 25.38,74.5 27.5,74.5 27.5,74.38
N$223
  Bottom 0.406: 34,68.5 29.12,68.5 | 27.5,68.5 29.12,68.5 | 29.12,68.5 29.12,70.12 32.75,70.12 | 32.88,70.12 32.75,70.12 | 32.75,70.12 32.75,68.62 33,68.62 33,68.88 29.5,68.88 | 29.38,68.88 29.5,68.88 | 29.5,68.88 29.5,69.88 32.38,69.88 32.38,69.12 29.75,69.12
N$224  (via drill 0.7 pad 1.68)
  other vias: 43.12,50.25
N$225
  Bottom 0.406: 34,66 33.88,66 | 33.88,66 33.88,62.75 | 22.88,71.25 37.25,71.25 37.25,66.5 34,66.5 | 29.5,66.5 29.25,66.5 29.25,67.25 27.25,67.25 27.25,66.38 | 27.25,66.38 22.5,66.38 22.5,71.12 37,71.12 37,70.75 22.88,70.75 22.88,70.38 37,70.38 37,70.12 | 37,70.12 37,69.88 34.12,69.88 34.12,70.12 36.88,70.12 | 37,70.12 36.88,70.12 | 36.88,70.12 36.88,66.62 34,66.62 | 34,66.62 34,66.75 | 34,66.75 33.88,66.75 33.88,67.75 | 33.88,67.88 33.88,68.62 36.62,68.62 36.62,68.75 36.5,68.75 36.5,69.5 34.38,69.5 34.38,68.75 | 34.38,68.75 34,68.75 | 34.38,68.75 36.25,68.75 36.25,69.25 34.62,69.25 34.62,68.88 36.5,68.88 36.5,66.88 34.12,66.88 34.12,68.25 36.12,68.25 | 36.12,68.25 36.12,68.38 | 36.12,68.25 36.12,67.12 34.62,67.12 34.62,67.25 34.5,67.25 34.5,67.88 | 34.5,67.88 34.5,68 34.38,68 34.38,67.25 35.88,67.25 35.88,67.88 34.75,67.88 | 34.5,67.88 34.75,67.88 | 34.75,67.88 34.75,67.62 35.75,67.62 | 27.25,66.38 29.5,66.38 29.5,66.5 | 29.5,66.5 33.88,66.5 | 34,66.5 34,66.62 | 34,66.75 34,66.88 22.62,66.88 22.62,66.62 33.5,66.62 33.5,67.25 22.75,67.25 22.75,67.38 22.88,67.38 22.88,70 27.75,70 27.75,70.12 27.62,70.12 27.62,67.5 22.75,67.5 22.75,67.75 23.12,67.75 23.12,67.88 33.88,67.88 | 33.88,67.88 33.88,67.75 | 33.88,67.75 33.75,67.75 33.75,67.5 27.75,67.5 27.75,67.62 27.38,67.62 27.38,67.75 27.25,67.75 27.25,69.75 23.25,69.75 23.25,68.12 33.38,68.12 33.38,68.38 23.62,68.38 23.62,69.5 23.88,69.5 23.88,68.5 24.25,68.5 24.25,69.62 24.88,69.62 24.88,69.25 | 24.88,68.88 24.88,68.5 27,68.5 27,68.88 | 27,68.88 27,69.25 24.88,69.25 | 24.88,69.25 24.88,68.88 | 24.88,68.88 27,68.88 | 27,68.88 27.88,68.88 27.88,68.62
  Bottom 0.406: 33.88,66 33.88,66.5 | 33.88,66.5 34,66.5 | 34,66.5 34,62.75 35.25,62.75
N$226
  Bottom 0.406: 27,47.88 24.12,47.88 24.12,61.75 24.12,61.88 24.12,66.5
N$227
  Bottom 0.406: 46.62,62.75 50,62.75 50,62.62
N$228
  Bottom 0.406: 72.5,9.5 46.75,9.5
N$229
  Bottom 0.406: 72.12,9.25 46.75,9.25 46.75,9.12
N$230
  Bottom 0.406: 46.75,9.75 72.38,9.75
N$231
  Bottom 0.406: 82.75,26.88 85,25
N$232
  Bottom 0.406: 85.25,24.88 91.5,19.75 91.38,20.5 89.88,21.5
N$233
  Bottom 0.406: 75.25,63.25 86.75,71
N$234
  Bottom 0.406: 76.88,53.5 77.38,54.12
N$235
  Bottom 0.406: 91.75,65.75 91.75,66 91.75,75.38 91.88,75.5 96.38,75.5 96.5,75.38 96.5,63.5 96.62,63.38 91.75,63.38 91.75,65.75

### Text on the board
Bottom: 64 | 49 | 1 | 48 | 1 | 2 | STM32F100 | 16 | 33 | 17 | 32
